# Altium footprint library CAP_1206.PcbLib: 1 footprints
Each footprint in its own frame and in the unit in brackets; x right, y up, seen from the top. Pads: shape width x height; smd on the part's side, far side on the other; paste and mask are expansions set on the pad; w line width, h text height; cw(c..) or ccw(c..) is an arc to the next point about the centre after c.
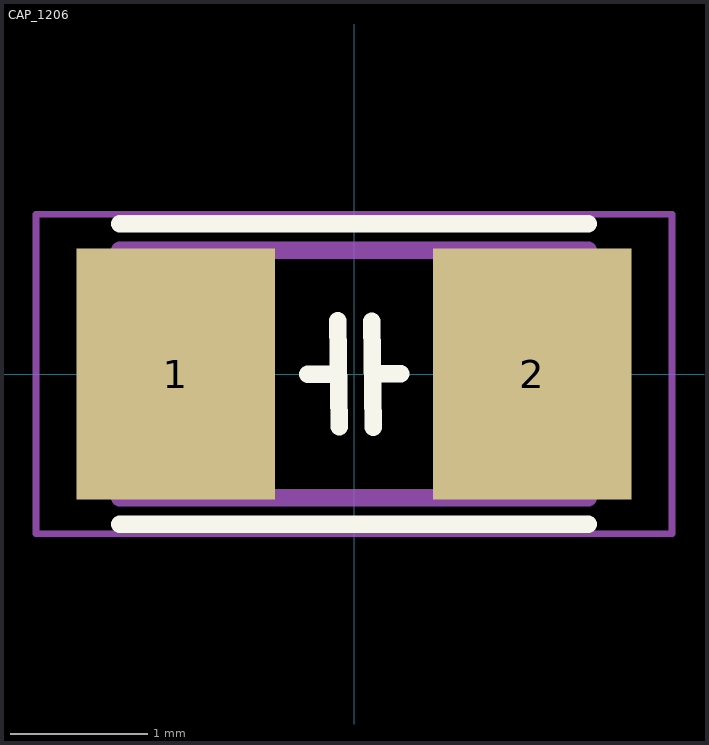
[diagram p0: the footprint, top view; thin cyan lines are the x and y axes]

## CAP_1206 [mm]
pads (2):
  rect 1.44x1.82 smd: 1(-1.295,0) 2(1.295,0)
Top Overlay:
  lines w0.127: -1.7,-1.09 1.7,-1.09 ; -1.7,1.09 1.7,1.09 ; -0.335,-0.002 -0.113,-0.002 ; -0.119,0.387 -0.107,-0.383 ; 0.129,0.384 0.14,-0.386 ; 0.16,0.002 0.34,0.002
Mechanical 13:
  lines w0.127: -1.7,-0.9 -1.7,0.9 1.7,0.9 1.7,-0.9 -1.7,-0.9
Mechanical 15:
  lines w0.05: -2.31,-1.16 -2.31,1.16 2.31,1.16 2.31,-1.16 -2.31,-1.16
3D body "CAP_1206.STEP": height 1.56, standoff -0.04, extent -1.6,-0.889 1.6,0.891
